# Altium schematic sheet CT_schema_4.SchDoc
size 255 x 159 mm
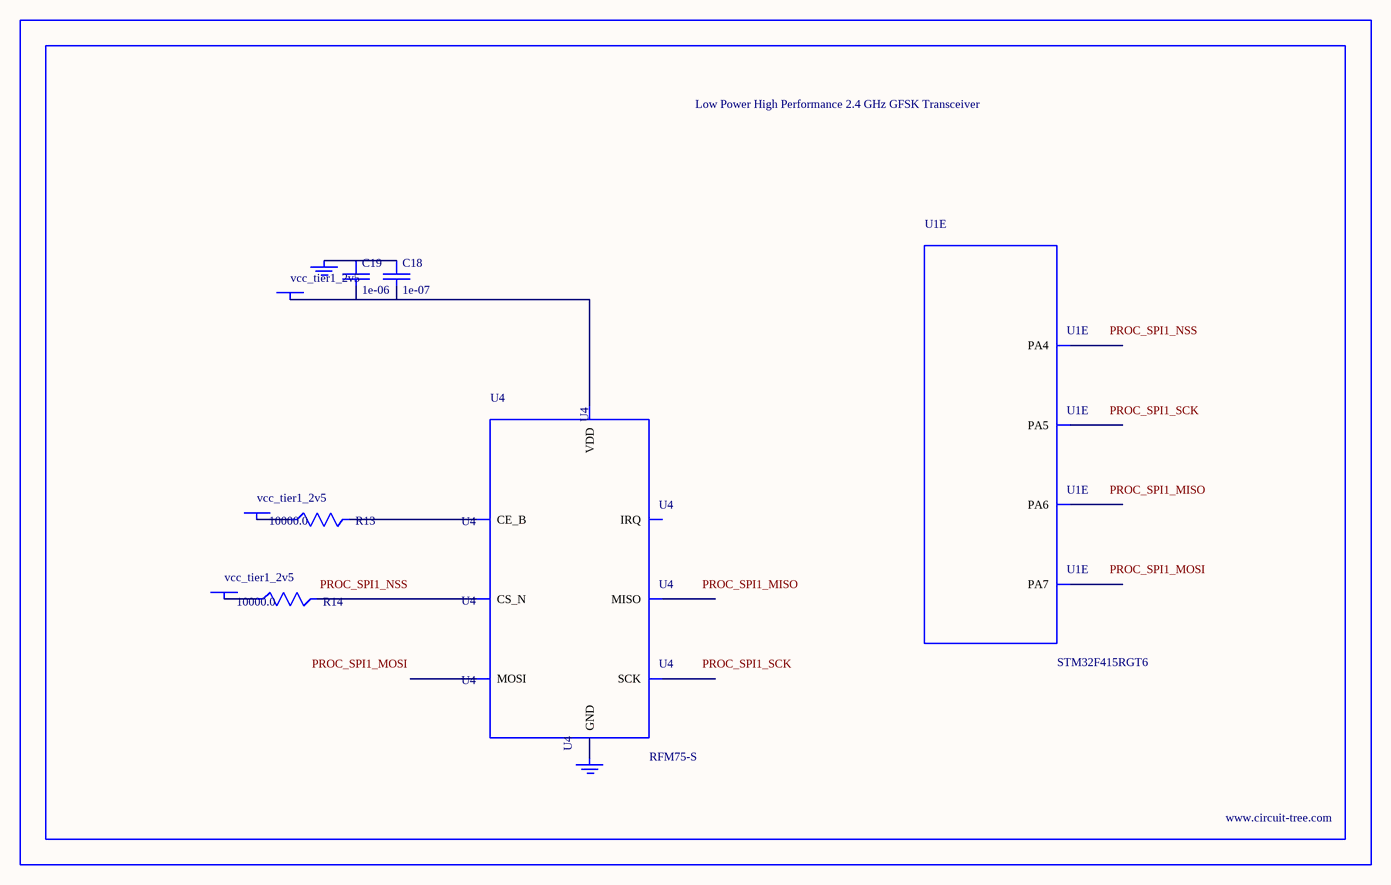
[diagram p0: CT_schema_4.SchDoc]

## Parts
BORDER3  (no value)
C18  1e-07  [C0402]
C19  1e-06  [C0603]
GND_INSTANCE_3_0  (no value)
GND_INSTANCE_3_1  (no value)
POWER_INSTANCE_3_0  vcc_tier1_2v5
POWER_INSTANCE_3_1  vcc_tier1_2v5
POWER_INSTANCE_3_2  vcc_tier1_2v5
R13  10000.0  [R0603]
R14  10000.0  [R0603]
U1  STM32F415RGT6  [LQFP64]  (part E of 7)
U4  RFM75-S  [RFM75-S]

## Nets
NetC18_1: C18.1 C19.1 GND_INSTANCE_3_0.0(GND)
NetC18_2: C18.2 C19.2 POWER_INSTANCE_3_0.0(PWR) U4.2(VDD)
NetGND_INSTANCE_3_1_0: GND_INSTANCE_3_1.0(GND) U4.1(GND)
NetPOWER_INSTANCE_3_1_0: POWER_INSTANCE_3_1.0(PWR) R13.1
NetPOWER_INSTANCE_3_2_0: POWER_INSTANCE_3_2.0(PWR) R14.1
NetR13_2: R13.2 U4.3(CE_B)
NetR14_2: R14.2 U4.4(CS_N)

Not connected (* = marked no-connect by the designer): U1 20(PA4) 21(PA5) 22(PA6) 23(PA7); U4 5(SCK) 6(MOSI) 7(MISO) 8(IRQ)

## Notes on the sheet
- Labels drawn without touching a wire or pin: PROC_SPI1_MISO, PROC_SPI1_MOSI, PROC_SPI1_NSS, PROC_SPI1_SCK

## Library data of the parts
BORDER3 = BORDER_PAGE3
C18 = C0402C104K3RACTU
C19 = C0603C105K3RACTU
GND_INSTANCE_3_0 GND_INSTANCE_3_1 = GND
POWER_INSTANCE_3_0-POWER_INSTANCE_3_2 = PWR
R13 R14 = RC0603JR-0710KL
